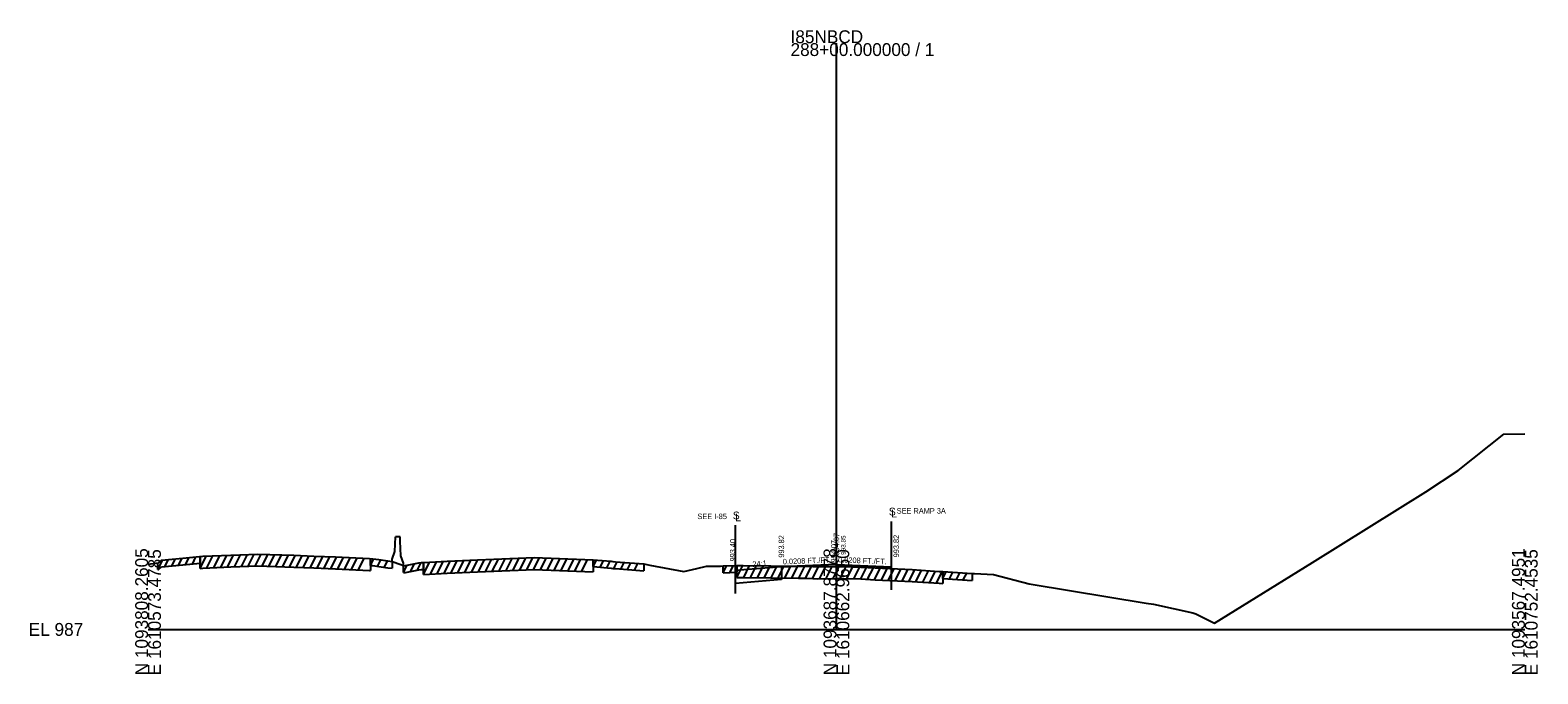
# Model space of a CAD drawing. Extents: x -26 to 1615432, y -20 to 1281970.
# Drawn here: x 974.3 to 1302.8, y 11990.3 to 12130.7 of the extents above; entities that cross this region are included whole.
import ezdxf

# ---------------------------------------------------------------- set-up
doc = ezdxf.new("R2010")
doc.units = 0
for name, color, linetype in [('CLS_MSE_MS_Wall', 7, 'Continuous'), ('HY_DR_DumbNodes', 7, 'Continuous'), ('RD_EX_Misc', 7, 'Continuous'), ('RD_GPK_XS_Cell', 7, 'Continuous'), ('RD_PD_DR_FlowCtrl', 7, 'Continuous'), ('RD_Sketch1', 7, 'Continuous'), ('RD_XE_Ground', 7, 'Continuous'), ('RD_XS_Base', 7, 'Continuous'), ('RD_XS_ExGround', 7, 'Continuous'), ('RD_XS_ExPaveRet', 7, 'Continuous'), ('RD_XS_MatchLine', 7, 'Continuous'), ('RD_XS_Pave', 7, 'Continuous'), ('RD_XS_PaveShd', 7, 'Continuous'), ('RD_XS_TX_Elev_EX', 7, 'Continuous'), ('RD_XS_TX_Elev_PR', 7, 'Continuous'), ('RD_XS_TX_MatchLine', 7, 'Continuous'), ('RD_XS_TX_ShdSlope', 7, 'Continuous'), ('RD_XS_TX_Slope', 7, 'Continuous')]:
    doc.layers.add(name, color=color, linetype=linetype)

msp = doc.modelspace()

# ---------------------------------------------------------------- linework, layer by layer
at = {"layer": 'HY_DR_DumbNodes'}
for p, q in [((1138, 12013.64), (1150, 12014.14)), ((1150, 12014.14), (1162, 12013.64))]:
    msp.add_line(p, q, dxfattribs=at)
at = {"layer": 'RD_EX_Misc'}
for p, q in [((1002.16, 12013.03), (1002.16, 12014.53)), ((1011.33, 12015.91), (1011.33, 12014.41)), ((1048.5, 12013.96), (1048.5, 12015.46)), ((1053.2, 12014.83), (1053.2, 12013.33)), ((1060.01, 12014.6), (1060.01, 12013.1)), ((1096.99, 12013.69), (1096.99, 12015.19)), ((1002.16, 12013.03), (1002.24, 12013.05)), ((1002.24, 12013.05), (1002.93, 12013.62)), ((1002.93, 12013.62), (1007.55, 12014.07)), ((1007.55, 12014.07), (1011.33, 12014.41)), ((1048.5, 12013.96), (1048.95, 12013.92)), ((1048.95, 12013.92), (1050.28, 12013.71)), ((1050.28, 12013.71), (1052.24, 12013.45)), ((1052.24, 12013.45), (1053.16, 12013.34)), ((1053.16, 12013.34), (1053.2, 12013.33)), ((1055.69, 12012.42), (1055.69, 12013.92)), ((1055.69, 12012.42), (1055.78, 12012.39)), ((1055.78, 12012.39), (1056.1, 12012.43)), ((1056.1, 12012.43), (1058.97, 12013.01)), ((1058.97, 12013.01), (1059.5, 12013.06)), ((1059.5, 12013.06), (1060.01, 12013.1)), ((1096.99, 12013.69), (1100.88, 12013.35)), ((1100.88, 12013.35), (1101.24, 12013.31)), ((1101.24, 12013.31), (1101.84, 12013.26)), ((1101.84, 12013.26), (1108.02, 12012.78)), ((1108.02, 12014.28), (1108.02, 12012.78)), ((1125.3, 12012.35), (1125.3, 12013.85)), ((1125.3, 12012.35), (1128.29, 12012.45)), ((1128.29, 12013.95), (1128.29, 12012.45)), ((1173.15, 12011.1), (1173.15, 12012.6)), ((1179.56, 12012.18), (1179.56, 12010.68)), ((1173.15, 12011.1), (1173.16, 12011.1)), ((1173.16, 12011.1), (1179.56, 12010.68)), ((1179.56, 12010.68), (1179.56, 12010.68))]:
    msp.add_line(p, q, dxfattribs=at)
at = {"layer": 'RD_GPK_XS_Cell'}
for p, q in [((1150, 12000), (1150, 12127.83)), ((1000, 12000), (1150, 12000)), ((1150, 12000), (1300, 12000))]:
    msp.add_line(p, q, dxfattribs=at)
at = {"layer": 'RD_PD_DR_FlowCtrl'}
for p, q in [((1138, 12013.64), (1150, 12014.14)), ((1150, 12014.14), (1162, 12013.64))]:
    msp.add_line(p, q, dxfattribs=at)
at = {"layer": 'RD_Sketch1'}
for p, q in [((1002.16, 12013.03), (1003.22, 12015.15)), ((1003.66, 12013.69), (1004.45, 12015.27)), ((1005.16, 12013.84), (1005.95, 12015.41)), ((1006.66, 12013.98), (1007.45, 12015.56)), ((1008.16, 12014.12), (1008.94, 12015.69)), ((1009.66, 12014.26), (1010.44, 12015.83)), ((1048.5, 12013.96), (1049.21, 12015.38)), ((1050, 12013.75), (1050.7, 12015.15)), ((1051.5, 12013.55), (1052.2, 12014.96)), ((1058.69, 12012.96), (1059.49, 12014.56)), ((1096.99, 12013.69), (1097.71, 12015.12)), ((1098.49, 12013.56), (1099.21, 12014.99)), ((1099.99, 12013.43), (1100.71, 12014.86)), ((1101.49, 12013.29), (1102.21, 12014.73)), ((1102.99, 12013.17), (1103.71, 12014.62)), ((1104.49, 12013.06), (1105.21, 12014.5)), ((1055.69, 12012.42), (1056.49, 12014.01)), ((1057.19, 12012.65), (1058.03, 12014.32)), ((1105.99, 12012.94), (1106.71, 12014.38)), ((1125.3, 12012.35), (1126.06, 12013.88)), ((1126.8, 12012.4), (1127.56, 12013.93)), ((1173.15, 12011.1), (1173.88, 12012.55)), ((1174.65, 12011), (1175.38, 12012.46)), ((1176.15, 12010.91), (1176.88, 12012.36)), ((1177.65, 12010.81), (1178.38, 12012.26))]:
    msp.add_line(p, q, dxfattribs=at)
at = {"layer": 'RD_XE_Ground'}
for p, q in [((1053.78, 12017), (1053.95, 12020.16)), ((1054.94, 12020.16), (1053.95, 12020.16)), ((1054.94, 12019.25), (1054.94, 12020.16)), ((1055.11, 12016.08), (1054.94, 12019.25)), ((1053.2, 12015.33), (1053.78, 12017)), ((1053.2, 12014.83), (1053.2, 12015.33)), ((1055.69, 12014.42), (1055.11, 12016.08)), ((1055.69, 12013.92), (1055.69, 12014.42))]:
    msp.add_line(p, q, dxfattribs=at)
at = {"layer": 'RD_XS_Base'}
for p, q in [((1128, 12010.03), (1128, 12012.81)), ((1138, 12013.64), (1138, 12010.86)), ((1141.87, 12013.8), (1143.36, 12013.78)), ((1143.36, 12013.78), (1144.83, 12013.69)), ((1144.83, 12013.69), (1145.78, 12013.66)), ((1145.78, 12013.66), (1150, 12013.7)), ((1150, 12013.7), (1150.45, 12013.71)), ((1150.45, 12013.71), (1151.62, 12013.71)), ((1151.62, 12013.71), (1155.34, 12013.6)), ((1155.34, 12013.6), (1158.42, 12013.42)), ((1158.42, 12013.42), (1162, 12013.25)), ((1138, 12010.86), (1128, 12010.03))]:
    msp.add_line(p, q, dxfattribs=at)
at = {"layer": 'RD_XS_ExGround'}
msp.add_lwpolyline([(1000, 12014.2), (1001.62, 12014.42), (1002.24, 12014.55), (1002.93, 12015.12), (1007.55, 12015.57), (1011.91, 12015.96), (1018.04, 12016.21), (1023.94, 12016.44), (1031.73, 12016.18), (1036.13, 12016), (1040.87, 12015.81), (1048.26, 12015.47), (1048.95, 12015.42), (1050.28, 12015.21), (1052.24, 12014.95), (1053.16, 12014.84), (1055.07, 12014.17), (1055.42, 12014.01), (1055.78, 12013.89), (1056.1, 12013.93), (1058.97, 12014.51), (1059.5, 12014.56), (1060.01, 12014.6), (1065.21, 12014.85), (1071.8, 12015.16), (1075.31, 12015.3), (1084.12, 12015.67), (1095.2, 12015.25), (1096.99, 12015.19), (1100.88, 12014.85), (1101.24, 12014.81), (1101.84, 12014.76), (1108.02, 12014.28), (1109.32, 12014.04), (1116.76, 12012.63), (1119.57, 12013.28), (1121.7, 12013.81), (1124.75, 12013.82), (1125.3, 12013.85), (1128.29, 12013.95), (1129.67, 12013.94), (1141.76, 12013.81), (1143.36, 12013.78), (1144.83, 12013.69), (1145.78, 12013.66), (1150, 12013.7), (1150.45, 12013.71), (1151.62, 12013.71), (1155.34, 12013.6), (1158.42, 12013.42), (1166.48, 12013.04), (1172.38, 12012.65), (1173.16, 12012.6), (1179.56, 12012.18), (1180.08, 12012.16), (1184.25, 12011.98), (1192.02, 12009.92), (1192.46, 12009.84), (1217.51, 12005.71), (1219.12, 12005.49), (1227.69, 12003.58), (1228.3, 12003.43), (1232.39, 12001.37), (1253.75, 12014.57), (1278.44, 12030.02), (1285.46, 12034.65), (1295.45, 12042.58), (1300, 12042.61)], dxfattribs=at)
at = {"layer": 'RD_XS_ExPaveRet'}
for p, q in [((1011.33, 12013.31), (1012.67, 12015.99)), ((1011.33, 12013.31), (1011.33, 12015.91)), ((1012.83, 12013.4), (1014.15, 12016.05)), ((1014.33, 12013.46), (1015.65, 12016.11)), ((1015.83, 12013.52), (1017.15, 12016.17)), ((1017.33, 12013.58), (1018.65, 12016.23)), ((1018.83, 12013.64), (1020.15, 12016.29)), ((1020.33, 12013.7), (1021.65, 12016.35)), ((1021.83, 12013.76), (1023.15, 12016.41)), ((1023.33, 12013.82), (1024.63, 12016.42)), ((1024.83, 12013.81), (1026.11, 12016.37)), ((1026.33, 12013.76), (1027.61, 12016.32)), ((1027.83, 12013.71), (1029.11, 12016.27)), ((1029.33, 12013.66), (1030.61, 12016.21)), ((1030.83, 12013.61), (1032.11, 12016.16)), ((1032.33, 12013.55), (1033.6, 12016.1)), ((1033.83, 12013.49), (1035.1, 12016.04)), ((1035.33, 12013.43), (1036.6, 12015.98)), ((1036.83, 12013.37), (1038.1, 12015.92)), ((1038.33, 12013.31), (1039.6, 12015.86)), ((1039.83, 12013.25), (1041.1, 12015.8)), ((1041.33, 12013.19), (1042.6, 12015.73)), ((1042.83, 12013.12), (1044.1, 12015.66)), ((1044.33, 12013.05), (1045.6, 12015.59)), ((1045.83, 12012.98), (1047.1, 12015.53)), ((1048.5, 12015.46), (1048.5, 12012.86)), ((1060.01, 12012), (1061.34, 12014.66)), ((1060.01, 12012), (1060.01, 12014.6)), ((1061.51, 12012.07), (1062.84, 12014.73)), ((1063.01, 12012.14), (1064.34, 12014.8)), ((1064.51, 12012.21), (1065.84, 12014.88)), ((1066.01, 12012.28), (1067.34, 12014.95)), ((1067.51, 12012.35), (1068.84, 12015.02)), ((1069.01, 12012.42), (1070.34, 12015.09)), ((1070.51, 12012.5), (1071.84, 12015.16)), ((1072.01, 12012.56), (1073.33, 12015.22)), ((1073.51, 12012.63), (1074.83, 12015.28)), ((1075.01, 12012.69), (1076.33, 12015.34)), ((1076.51, 12012.75), (1077.83, 12015.4)), ((1078.01, 12012.81), (1079.33, 12015.47)), ((1079.51, 12012.87), (1080.83, 12015.53)), ((1081.01, 12012.94), (1082.33, 12015.59)), ((1082.51, 12013), (1083.83, 12015.66)), ((1084.01, 12013.06), (1085.29, 12015.62)), ((1085.51, 12013.02), (1086.78, 12015.57)), ((1087.01, 12012.96), (1088.28, 12015.51)), ((1088.51, 12012.9), (1089.78, 12015.46)), ((1090.01, 12012.85), (1091.28, 12015.4)), ((1091.51, 12012.79), (1092.78, 12015.34)), ((1093.01, 12012.74), (1094.28, 12015.29)), ((1094.51, 12012.68), (1095.78, 12015.23)), ((1096.99, 12015.19), (1096.99, 12012.59)), ((1011.33, 12013.31), (1011.91, 12013.36)), ((1011.91, 12013.36), (1018.04, 12013.61)), ((1018.04, 12013.61), (1023.94, 12013.84)), ((1023.94, 12013.84), (1031.73, 12013.58)), ((1031.73, 12013.58), (1036.13, 12013.4)), ((1036.13, 12013.4), (1040.87, 12013.21)), ((1040.87, 12013.21), (1048.26, 12012.87)), ((1048.26, 12012.87), (1048.5, 12012.86)), ((1060.01, 12012), (1065.21, 12012.25)), ((1065.21, 12012.25), (1071.8, 12012.56)), ((1071.8, 12012.56), (1075.31, 12012.7)), ((1075.31, 12012.7), (1084.12, 12013.07)), ((1084.12, 12013.07), (1095.2, 12012.65)), ((1095.2, 12012.65), (1096.99, 12012.59)), ((1128.29, 12011.35), (1128.29, 12013.95)), ((1128.29, 12011.35), (1129.59, 12013.94)), ((1128.29, 12011.35), (1129.67, 12011.34)), ((1129.67, 12011.34), (1141.76, 12011.21)), ((1129.79, 12011.34), (1131.09, 12013.93)), ((1131.29, 12011.33), (1132.59, 12013.91)), ((1132.79, 12011.31), (1134.09, 12013.89)), ((1134.29, 12011.29), (1135.59, 12013.88)), ((1135.79, 12011.27), (1137.09, 12013.86)), ((1137.29, 12011.26), (1138.59, 12013.84)), ((1138.79, 12011.24), (1140.09, 12013.82)), ((1140.29, 12011.22), (1141.59, 12013.81)), ((1141.76, 12011.21), (1143.36, 12011.18)), ((1141.79, 12011.21), (1143.08, 12013.78)), ((1143.29, 12011.18), (1144.56, 12013.7)), ((1143.36, 12011.18), (1144.83, 12011.09)), ((1144.79, 12011.09), (1146.08, 12013.66)), ((1146.29, 12011.06), (1147.6, 12013.68)), ((1147.79, 12011.08), (1149.1, 12013.69)), ((1149.29, 12011.1), (1150.6, 12013.71)), ((1150.79, 12011.11), (1152.09, 12013.7)), ((1152.29, 12011.09), (1153.58, 12013.66)), ((1153.79, 12011.05), (1155.08, 12013.61)), ((1155.29, 12011.01), (1156.56, 12013.53)), ((1156.79, 12010.92), (1158.06, 12013.44)), ((1158.29, 12010.83), (1159.56, 12013.37)), ((1159.79, 12010.76), (1161.06, 12013.3)), ((1161.29, 12010.69), (1162.56, 12013.23)), ((1162.79, 12010.61), (1164.06, 12013.15)), ((1164.29, 12010.54), (1165.56, 12013.08)), ((1165.79, 12010.47), (1167.06, 12013)), ((1167.29, 12010.39), (1168.55, 12012.9)), ((1168.79, 12010.29), (1170.05, 12012.8)), ((1170.29, 12010.19), (1171.55, 12012.7)), ((1171.79, 12010.09), (1173.05, 12012.61)), ((1173.15, 12012.6), (1173.15, 12010)), ((1144.83, 12011.09), (1145.78, 12011.06)), ((1145.78, 12011.06), (1150, 12011.1)), ((1150, 12011.1), (1150.45, 12011.11)), ((1150.45, 12011.11), (1151.62, 12011.11)), ((1151.62, 12011.11), (1155.34, 12011)), ((1155.34, 12011), (1158.42, 12010.82)), ((1158.42, 12010.82), (1166.48, 12010.44)), ((1166.48, 12010.44), (1172.38, 12010.05)), ((1172.38, 12010.05), (1173.15, 12010))]:
    msp.add_line(p, q, dxfattribs=at)
at = {"layer": 'RD_XS_MatchLine'}
for p, q in [((1128, 12013.94), (1128, 12012.81)), ((1162, 12013.25), (1162, 12013.64))]:
    msp.add_line(p, q, dxfattribs=at)
at = {"layer": 'RD_XS_Pave'}
for q in [(1138, 12013.64), (1162, 12013.64)]:
    msp.add_line((1150, 12014.14), q, dxfattribs=at)
at = {"layer": 'RD_XS_PaveShd'}
msp.add_line((1138, 12013.64), (1128, 12012.81), dxfattribs=at)
at = {"layer": 'RD_XS_TX_MatchLine'}
for p, q in [((1128, 12012.81), (1128, 12022.7)), ((1162, 12013.64), (1162, 12023.53)), ((1128, 12007.81), (1128, 12012.81)), ((1162, 12008.64), (1162, 12013.64))]:
    msp.add_line(p, q, dxfattribs=at)

# ---------------------------------------------------------------- texts
at = {"layer": 'CLS_MSE_MS_Wall'}
for s, p in [('SEE I-85', (1119.71, 12024.05)), ('SEE RAMP 3A', (1163.13, 12025.25))]:
    msp.add_text(s, height=1.2, dxfattribs=at).set_placement(p)
at = {"layer": 'HY_DR_DumbNodes'}
msp.add_text(' 994.07', height=1.2, rotation=90, dxfattribs=at).set_placement((1150, 12014.14))
at = {"layer": 'RD_GPK_XS_Cell'}
for s, p in [('I85NBCD', (1140, 12127.83)), ('288+00.000000 / 1', (1140, 12125.03)), ('EL 987', (974, 11998.6))]:
    msp.add_text(s, height=2.8, dxfattribs=at).set_placement(p)
for s, p in [('N 1093808.2605', (1000, 11990)), ('E 1610573.4785', (1002.8, 11990)), ('N 1093687.8778', (1150, 11990)), ('E 1610662.9660', (1152.8, 11990)), ('N 1093567.4951', (1300, 11990)), ('E 1610752.4535', (1302.8, 11990))]:
    msp.add_text(s, height=2.8, rotation=90, dxfattribs=at).set_placement(p)
at = {"layer": 'RD_PD_DR_FlowCtrl'}
msp.add_text(' 994.07', height=1.2, rotation=90, dxfattribs=at).set_placement((1150, 12014.14))
at = {"layer": 'RD_XS_TX_Elev_EX'}
msp.add_text('993.85', height=1, rotation=90, dxfattribs=at).set_placement((1152, 12016.26))
at = {"layer": 'RD_XS_TX_Elev_PR'}
for s, p in [('993.40', (1128, 12014.81)), ('993.82', (1138.6, 12015.64)), ('994.07', (1150.6, 12016.14)), ('993.82', (1163.63, 12015.71))]:
    msp.add_text(s, height=1.2, rotation=90, dxfattribs=at).set_placement(p)
at = {"layer": 'RD_XS_TX_MatchLine'}
for s, p in [('S', (1127.42, 12024.01)), ('L', (1127.93, 12023.58)), ('S', (1161.42, 12024.85)), ('L', (1161.93, 12024.41))]:
    msp.add_text(s, height=1.68, dxfattribs=at).set_placement(p)
at = {"layer": 'RD_XS_TX_ShdSlope'}
msp.add_text('24:1', height=1.2, rotation=4.7636, dxfattribs=at).set_placement((1131.75, 12013.62))
at = {"layer": 'RD_XS_TX_Slope'}
for rotation, p in [(2.3859, (1138.34, 12014.16)), (357.6141, (1150.35, 12014.63))]:
    msp.add_text('0.0208 FT./FT.', height=1.2, rotation=rotation, dxfattribs=at).set_placement(p)

doc.saveas('drawing.dxf')
